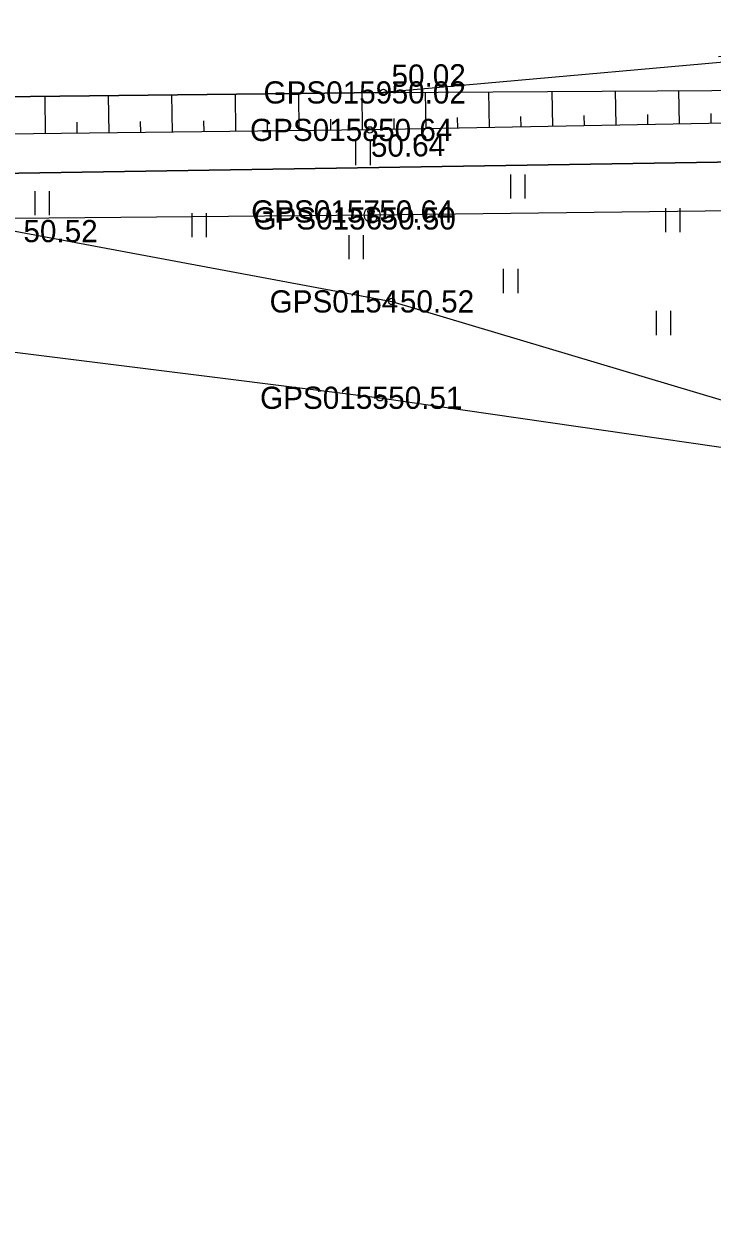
# Model space of a CAD drawing. Extents: x 551623 to 559850, y 6561220 to 6567135.
# Drawn here: x 555955.52 to 555977.24, y 6565327.62 to 6565365.09 of the extents above; entities that cross this region are included whole.
import ezdxf

# ---------------------------------------------------------------- set-up
doc = ezdxf.new("R2010")
doc.units = 0
for name, color, linetype in [('HALJASTUS', 7, 'Continuous'), ('KORGUS-EH2000', 7, 'Continuous'), ('KPOHULIIN', 7, 'Continuous'), ('MOOTKORG-EH2000', 7, 'Continuous'), ('MOOTMPUNKT', 7, 'Continuous'), ('MOOTNR', 7, 'Continuous'), ('MOOTPIIR', 7, 'Continuous'), ('PIIR', 7, 'Continuous'), ('POST', 7, 'Continuous'), ('RELJEEF', 7, 'Continuous')]:
    doc.layers.add(name, color=color, linetype=linetype)

msp = doc.modelspace()

# ---------------------------------------------------------------- linework, layer by layer
at = {"layer": 'HALJASTUS'}
for p, q in [((555965.989, 6565361.399), (555965.989, 6565360.637)), ((555966.444, 6565361.399), (555966.444, 6565360.637)), ((555970.876, 6565360.34), (555970.876, 6565359.579)), ((555971.331, 6565360.34), (555971.331, 6565359.579)), ((555955.868, 6565359.812), (555955.868, 6565359.051)), ((555956.323, 6565359.812), (555956.323, 6565359.051)), ((555960.82, 6565359.121), (555960.82, 6565358.36)), ((555961.275, 6565359.121), (555961.275, 6565358.36)), ((555975.763, 6565359.281), (555975.763, 6565358.52)), ((555976.218, 6565359.281), (555976.218, 6565358.52)), ((555965.772, 6565358.43), (555965.772, 6565357.668)), ((555966.227, 6565358.43), (555966.227, 6565357.668)), ((555970.646, 6565357.359), (555970.646, 6565356.598)), ((555971.101, 6565357.359), (555971.101, 6565356.598)), ((555975.467, 6565356.034), (555975.467, 6565355.273)), ((555975.922, 6565356.034), (555975.922, 6565355.273))]:
    msp.add_line(p, q, dxfattribs=at)
msp.add_lwpolyline([(555785.422, 6565354.502), (555797.657, 6565356.597), (555822.006, 6565356.167), (555839.027, 6565357.099), (555858.223, 6565356.795), (555871.496, 6565354.829), (555880.675, 6565355.554), (555884.247, 6565356.161), (555900.004, 6565357.858), (555919.022, 6565357.654), (555943.248, 6565358.425), (555955.251, 6565358.554), (555967.126, 6565356.336), (555981.596, 6565352.013), (555991.477, 6565347.286)], dxfattribs=at)
at = {"layer": 'KORGUS-EH2000'}
for centre in [(555966.865, 6565362.926), (555966.438, 6565361.744), (555967.126, 6565356.336), (555966.756, 6565353.298)]:
    msp.add_circle(centre, 0.1, dxfattribs=at)
at = {"layer": 'KPOHULIIN'}
msp.add_lwpolyline([(555766.29, 6565358.132), (555774.476, 6565357.809), (555774.476, 6565357.809), (555822.758, 6565358.143), (555870.36, 6565358.416), (555918.911, 6565358.624), (555918.911, 6565358.624), (555966.511, 6565359.063), (556012.012, 6565359.614), (556063.102, 6565345.172), (556063.102, 6565345.172), (556112.628, 6565331.115), (556160.567, 6565309.951), (556211.02, 6565287.529)], dxfattribs=at)
at = {"layer": 'MOOTMPUNKT'}
for centre in [(555966.865, 6565362.926), (555966.438, 6565361.744), (555966.475, 6565359.173), (555966.547, 6565358.953), (555967.126, 6565356.336), (555966.756, 6565353.298)]:
    msp.add_circle(centre, 0.1, dxfattribs=at)
at = {"layer": 'MOOTPIIR'}
for points in [[(556057.929, 6565353.821), (556039.198, 6565356.19), (556028.747, 6565357.937), (556026.171, 6565358.357), (556019.769, 6565359.212), (556019.902, 6565364.745), (556021.558, 6565374.265), (556015.152, 6565374.331), (556012.73, 6565375.394), (555993.907, 6565375.821), (555986.511, 6565374.867), (555981.259, 6565364.203), (555966.865, 6565362.926), (555942.733, 6565362.646), (555918.997, 6565362.459), (555899.983, 6565361.794), (555880.558, 6565361.528), (555870.644, 6565361.764), (555852.219, 6565361.421)], [(555839.435, 6565355.215), (555871.496, 6565354.829), (555900.084, 6565356.085), (555918.855, 6565355.549), (555942.97, 6565356.268), (555966.756, 6565353.298), (555985.371, 6565350.605), (555996.731, 6565349.216), (556009.016, 6565348.025), (556019.674, 6565346.939), (556026.62, 6565346.439), (556031.505, 6565345.235), (556038.736, 6565344.782), (556063.163, 6565343.594)]]:
    msp.add_lwpolyline(points, dxfattribs=at)
at = {"layer": 'PIIR'}
for points in [[(555860.69, 6565787.05), (556134.83, 6565867.67), (556136.76, 6565868.24), (556138.68, 6565868.81), (556304.72, 6565917.64), (556407.28, 6565947.65), (556409.2, 6565948.21), (556411.12, 6565948.77), (556555.39, 6565990.98), (556602.55, 6565855.41), (556340.11, 6565662.55), (556145.23, 6565518.55), (556122.95, 6565328.71), (556065.95, 6565349.3), (555986.85, 6565360.88), (555889.86, 6565359.34), (555877.35, 6565546.73)], [(555766.77, 6565362.31), (555785.15, 6565359.9), (555792.17, 6565359.86), (555889.86, 6565359.34), (555986.85, 6565360.88), (556065.95, 6565349.3), (556122.95, 6565328.71), (556199.38, 6565295.85), (556198.85, 6565282.81), (556195.83, 6565275.41), (556189.32, 6565262.35), (556176.88, 6565235.57), (556133.25, 6565139.15), (556097.67, 6565060.64), (555982.17, 6564796.57), (555965.54, 6564731.83), (555935.2, 6564801.96), (555871.92, 6565015.39), (555870.22, 6565021.13), (555867.36, 6565030.76)]]:
    msp.add_lwpolyline(points, close=True, dxfattribs=at)
at = {"layer": 'POST'}
msp.add_circle((555966.511, 6565359.063), 0.25, dxfattribs=at)
at = {"layer": 'RELJEEF'}
for p, q in [((555960.21, 6565361.67), (555960.196, 6565362.849)), ((555962.21, 6565361.694), (555962.196, 6565362.872)), ((555964.21, 6565361.717), (555964.196, 6565362.895)), ((555966.21, 6565361.741), (555966.196, 6565362.918)), ((555968.21, 6565361.777), (555968.188, 6565362.934)), ((555970.209, 6565361.814), (555970.188, 6565362.947)), ((555972.209, 6565361.851), (555972.188, 6565362.959)), ((555974.208, 6565361.889), (555974.188, 6565362.972)), ((555976.208, 6565361.926), (555976.188, 6565362.984)), ((555956.211, 6565361.622), (555956.197, 6565362.802)), ((555958.21, 6565361.646), (555958.196, 6565362.825)), ((555967.21, 6565361.758), (555967.203, 6565362.109)), ((555969.209, 6565361.795), (555969.203, 6565362.139)), ((555971.209, 6565361.833), (555971.203, 6565362.169)), ((555973.209, 6565361.87), (555973.203, 6565362.199)), ((555975.208, 6565361.907), (555975.202, 6565362.229)), ((555977.208, 6565361.945), (555977.202, 6565362.258)), ((555957.21, 6565361.634), (555957.206, 6565361.988)), ((555959.21, 6565361.658), (555959.206, 6565362.012)), ((555961.21, 6565361.682), (555961.206, 6565362.035)), ((555963.21, 6565361.705), (555963.206, 6565362.059)), ((555965.21, 6565361.729), (555965.206, 6565362.082))]:
    msp.add_line(p, q, dxfattribs=at)
for points in [[(555977.434, 6565364.06), (555981.259, 6565364.203), (555982.4, 6565363.023), (555981.07, 6565362.017), (555966.438, 6565361.744), (555942.559, 6565361.46), (555918.67, 6565361.158), (555899.588, 6565360.623), (555880.605, 6565360.164), (555870.862, 6565359.746), (555858.243, 6565359.74), (555839.055, 6565359.56), (555820.21, 6565359.553), (555797.755, 6565359.993), (555784.547, 6565360.474), (555784.137, 6565361.851), (555784.785, 6565363.462), (555797.779, 6565363.82), (555819.876, 6565363.911), (555838.744, 6565363.561), (555851.243, 6565363.431)], [(555785.165, 6565362.242), (555796.742, 6565361.819), (555819.94, 6565361.437), (555839.062, 6565361.413), (555858.506, 6565361.425), (555870.644, 6565361.764), (555880.558, 6565361.528), (555899.983, 6565361.794), (555918.997, 6565362.459), (555942.733, 6565362.646), (555966.865, 6565362.926), (555982.4, 6565363.023)]]:
    msp.add_lwpolyline(points, dxfattribs=at)

# ---------------------------------------------------------------- texts
at = {"layer": 'KORGUS-EH2000'}
for s, rotation, p in [(' 50.02', 0.36, (555966.864, 6565363.101)), (' 50.64', 0.6802, (555966.214, 6565360.888))]:
    msp.add_text(s, height=0.7, rotation=rotation, dxfattribs=at).set_placement(p)
for s, p in [(' 50.52', (555955.251, 6565358.204)), (' 50.52', (555967.126, 6565355.986)), (' 50.51', (555966.756, 6565352.948))]:
    msp.add_text(s, height=0.7, dxfattribs=at).set_placement(p)
at = {"layer": 'MOOTKORG-EH2000'}
for s, p in [(' 50.02', (555966.865, 6565362.576)), (' 50.64', (555966.438, 6565361.394)), (' 50.64', (555966.475, 6565358.823)), (' 50.50', (555966.547, 6565358.603)), (' 50.52', (555955.251, 6565358.204)), (' 50.52', (555967.126, 6565355.986)), (' 50.51', (555966.756, 6565352.948))]:
    msp.add_text(s, height=0.7, dxfattribs=at).set_placement(p)
at = {"layer": 'MOOTNR'}
for s, p in [('GPS0159 ', (555963.085, 6565362.576)), ('GPS0158 ', (555962.658, 6565361.394)), ('GPS0157 ', (555962.695, 6565358.823)), ('GPS0156 ', (555962.767, 6565358.603)), ('GPS0154 ', (555963.276, 6565355.986)), ('GPS0155 ', (555962.976, 6565352.948))]:
    msp.add_text(s, height=0.7, dxfattribs=at).set_placement(p)

doc.saveas('drawing.dxf')
